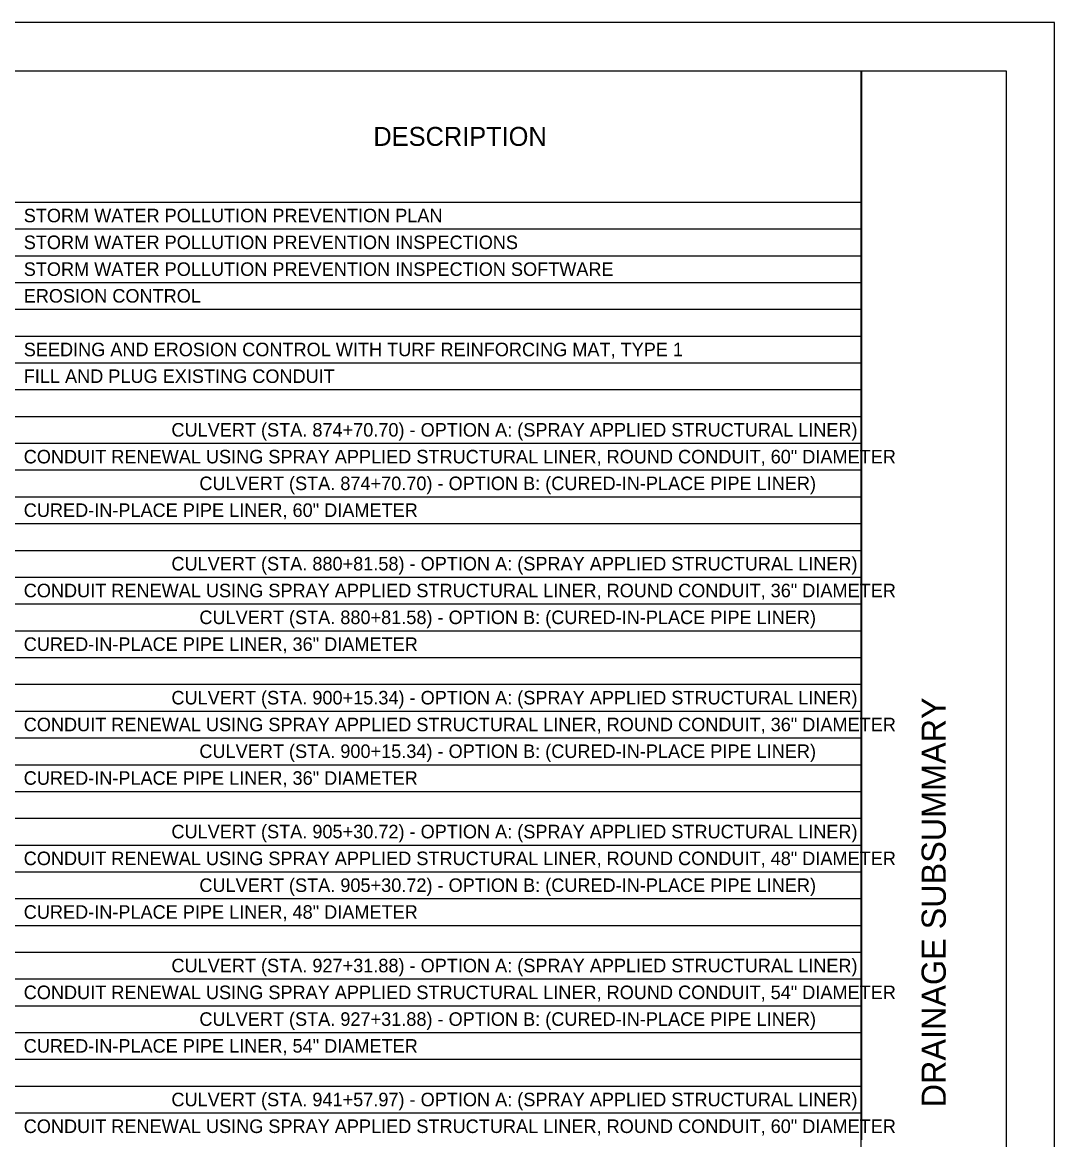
# Model space of a CAD drawing. Extents: x 0.2 to 34.2, y 0 to 22.
# Drawn here: x 23.52 to 34.19, y 10.48 to 22.03 of the extents above; entities that cross this region are included whole.
import ezdxf

# ---------------------------------------------------------------- set-up
doc = ezdxf.new("R2010")
doc.units = 0
for name, color, linetype in [('Default', 7, 'Continuous'), ('SH_Border', 7, 'Continuous'), ('SH_Cut_Line', 7, 'Continuous'), ('SH_Data', 7, 'Continuous')]:
    doc.layers.add(name, color=color, linetype=linetype)

msp = doc.modelspace()

# ---------------------------------------------------------------- linework, layer by layer
at = {"layer": 'Default'}
for p, q in [((16.555, 21.525), (32.196, 21.525)), ((32.196, 21.525), (32.196, 21.249)), ((32.196, 21.249), (32.196, 20.972)), ((32.196, 20.972), (32.196, 20.722)), ((32.196, 20.722), (32.196, 20.445)), ((32.196, 20.445), (32.196, 20.168)), ((16.555, 20.168), (32.196, 20.168)), ((32.196, 20.168), (32.196, 19.891)), ((16.555, 19.891), (32.196, 19.891)), ((32.196, 19.891), (32.196, 19.615)), ((16.555, 19.615), (32.196, 19.615)), ((32.196, 19.615), (32.196, 19.338)), ((16.555, 19.338), (32.196, 19.338)), ((32.196, 19.338), (32.196, 19.061)), ((16.555, 19.061), (32.196, 19.061)), ((32.196, 19.061), (32.196, 18.785)), ((16.555, 18.785), (32.196, 18.785)), ((32.196, 18.785), (32.196, 18.508)), ((16.555, 18.508), (32.196, 18.508)), ((32.196, 18.508), (32.196, 18.231)), ((16.555, 18.231), (32.196, 18.231)), ((32.196, 18.231), (32.196, 17.954)), ((16.555, 17.954), (32.196, 17.954)), ((32.196, 17.954), (32.196, 17.678)), ((16.555, 17.678), (32.196, 17.678)), ((32.196, 17.678), (32.196, 17.401)), ((16.555, 17.401), (32.196, 17.401)), ((32.196, 17.401), (32.196, 17.124)), ((16.555, 17.124), (32.196, 17.124)), ((32.196, 17.124), (32.196, 16.848)), ((16.555, 16.848), (32.196, 16.848)), ((32.196, 16.848), (32.196, 16.571)), ((16.555, 16.571), (32.196, 16.571)), ((32.196, 16.571), (32.196, 16.294)), ((16.555, 16.294), (32.196, 16.294)), ((32.196, 16.294), (32.196, 16.018)), ((16.555, 16.018), (32.196, 16.018)), ((32.196, 16.018), (32.196, 15.741)), ((16.555, 15.741), (32.196, 15.741)), ((32.196, 15.741), (32.196, 15.464)), ((16.555, 15.464), (32.196, 15.464)), ((32.196, 15.464), (32.196, 15.187)), ((16.555, 15.187), (32.196, 15.187)), ((32.196, 15.187), (32.196, 14.911)), ((16.555, 14.911), (32.196, 14.911)), ((32.196, 14.911), (32.196, 14.634)), ((16.555, 14.634), (32.196, 14.634)), ((32.196, 14.634), (32.196, 14.357)), ((16.555, 14.357), (32.196, 14.357)), ((32.196, 14.357), (32.196, 14.081)), ((16.555, 14.081), (32.196, 14.081)), ((32.196, 14.081), (32.196, 13.804)), ((16.555, 13.804), (32.196, 13.804)), ((32.196, 13.804), (32.196, 13.527)), ((16.555, 13.527), (32.196, 13.527)), ((32.196, 13.527), (32.196, 13.25)), ((16.555, 13.25), (32.196, 13.25)), ((32.196, 13.25), (32.196, 12.974)), ((16.555, 12.974), (32.196, 12.974)), ((32.196, 12.974), (32.196, 12.697)), ((16.555, 12.697), (32.196, 12.697)), ((32.196, 12.697), (32.196, 12.42)), ((16.555, 12.42), (32.196, 12.42)), ((32.196, 12.42), (32.196, 12.144)), ((16.555, 12.144), (32.196, 12.144)), ((32.196, 12.144), (32.196, 11.867)), ((16.555, 11.867), (32.196, 11.867)), ((32.196, 11.867), (32.196, 11.59)), ((16.555, 11.59), (32.196, 11.59)), ((32.196, 11.59), (32.196, 11.314)), ((16.555, 11.314), (32.196, 11.314)), ((32.196, 11.314), (32.196, 11.037)), ((16.555, 11.037), (32.196, 11.037)), ((32.196, 11.037), (32.196, 10.76)), ((16.555, 10.76), (32.196, 10.76)), ((32.196, 10.76), (32.196, 10.483))]:
    msp.add_line(p, q, dxfattribs=at)
at = {"layer": 'SH_Border'}
msp.add_line((32.192, 0.525), (32.192, 21.525), dxfattribs=at)
msp.add_lwpolyline([(1.692, 21.525), (33.692, 21.525), (33.692, 0.525), (1.692, 0.525)], close=True, dxfattribs=at)
at = {"layer": 'SH_Cut_Line'}
msp.add_lwpolyline([(0.192, 0.025), (34.192, 0.025), (34.192, 22.025), (0.192, 22.025)], close=True, dxfattribs=at)

# ---------------------------------------------------------------- texts
at = {"layer": 'Default'}
for s, height, p in [('DESCRIPTION', 0.196, (27.152, 20.749)), ('STORM WATER POLLUTION PREVENTION PLAN', 0.14, (23.539, 19.96)), ('STORM WATER POLLUTION PREVENTION INSPECTIONS', 0.14, (23.539, 19.683)), ('STORM WATER POLLUTION PREVENTION INSPECTION SOFTWARE', 0.14, (23.539, 19.406)), ('EROSION CONTROL', 0.14, (23.539, 19.13)), ('SEEDING AND EROSION CONTROL WITH TURF REINFORCING MAT, TYPE 1', 0.14, (23.539, 18.576)), ('FILL AND PLUG EXISTING CONDUIT', 0.14, (23.539, 18.3)), ('CULVERT (STA. 874+70.70) - OPTION A: (SPRAY APPLIED STRUCTURAL LINER)', 0.14, (25.065, 17.746)), ('CONDUIT RENEWAL USING SPRAY APPLIED STRUCTURAL LINER, ROUND CONDUIT, 60" DIAMETER', 0.14, (23.539, 17.469)), ('CULVERT (STA. 874+70.70) - OPTION B: (CURED-IN-PLACE PIPE LINER)', 0.14, (25.354, 17.193)), ('CURED-IN-PLACE PIPE LINER, 60" DIAMETER', 0.14, (23.539, 16.916)), ('CULVERT (STA. 880+81.58) - OPTION A: (SPRAY APPLIED STRUCTURAL LINER)', 0.14, (25.065, 16.363)), ('CONDUIT RENEWAL USING SPRAY APPLIED STRUCTURAL LINER, ROUND CONDUIT, 36" DIAMETER', 0.14, (23.539, 16.086)), ('CULVERT (STA. 880+81.58) - OPTION B: (CURED-IN-PLACE PIPE LINER)', 0.14, (25.354, 15.809)), ('CURED-IN-PLACE PIPE LINER, 36" DIAMETER', 0.14, (23.539, 15.532)), ('CULVERT (STA. 900+15.34) - OPTION A: (SPRAY APPLIED STRUCTURAL LINER)', 0.14, (25.065, 14.979)), ('CONDUIT RENEWAL USING SPRAY APPLIED STRUCTURAL LINER, ROUND CONDUIT, 36" DIAMETER', 0.14, (23.539, 14.702)), ('CULVERT (STA. 900+15.34) - OPTION B: (CURED-IN-PLACE PIPE LINER)', 0.14, (25.354, 14.426)), ('CURED-IN-PLACE PIPE LINER, 36" DIAMETER', 0.14, (23.539, 14.149)), ('CULVERT (STA. 905+30.72) - OPTION A: (SPRAY APPLIED STRUCTURAL LINER)', 0.14, (25.065, 13.596)), ('CONDUIT RENEWAL USING SPRAY APPLIED STRUCTURAL LINER, ROUND CONDUIT, 48" DIAMETER', 0.14, (23.539, 13.319)), ('CULVERT (STA. 905+30.72) - OPTION B: (CURED-IN-PLACE PIPE LINER)', 0.14, (25.354, 13.042)), ('CURED-IN-PLACE PIPE LINER, 48" DIAMETER', 0.14, (23.539, 12.765)), ('CULVERT (STA. 927+31.88) - OPTION A: (SPRAY APPLIED STRUCTURAL LINER)', 0.14, (25.065, 12.212)), ('CONDUIT RENEWAL USING SPRAY APPLIED STRUCTURAL LINER, ROUND CONDUIT, 54" DIAMETER', 0.14, (23.539, 11.935)), ('CULVERT (STA. 927+31.88) - OPTION B: (CURED-IN-PLACE PIPE LINER)', 0.14, (25.354, 11.659)), ('CURED-IN-PLACE PIPE LINER, 54" DIAMETER', 0.14, (23.539, 11.382)), ('CULVERT (STA. 941+57.97) - OPTION A: (SPRAY APPLIED STRUCTURAL LINER)', 0.14, (25.065, 10.828)), ('CONDUIT RENEWAL USING SPRAY APPLIED STRUCTURAL LINER, ROUND CONDUIT, 60" DIAMETER', 0.14, (23.539, 10.552))]:
    msp.add_text(s, height=height, dxfattribs=at).set_placement(p)
at = {"layer": 'SH_Data'}
msp.add_text('DRAINAGE SUBSUMMARY', height=0.25, rotation=90, dxfattribs=at).set_placement((33.067, 10.817))

doc.saveas('drawing.dxf')
